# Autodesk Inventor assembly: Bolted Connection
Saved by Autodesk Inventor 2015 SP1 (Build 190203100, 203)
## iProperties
Created: 2014-12
Part Number: Bolted Connection
Document SubType Name: Assembly
Designer: rsheridan
ClientObjectVersion: 1
Author: rsheridan
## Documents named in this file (4)
- \\psf\Home\Documents\Inventor\Sau Paulo Chimnea\Base Assembly\Design Accelerator\Bolted Connection1.iam
- \\psf\Home\Documents\Inventor\Sau Paulo Chimnea\DIN EN ISO 7046-2 H - M5x35 - 8.8 - H1.ipt
- \\psf\Home\Documents\Inventor\Sau Paulo Chimnea\ISO 7089 - 5 - 140 HV(1).ipt
- \\psf\Home\Documents\Inventor\Sau Paulo Chimnea\ISO 4032 - M5ISO.ipt
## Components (9 placed, 3 different names)
1. DIN EN ISO 7046-2 H - M5x35 - 8.8 - H1:1
2. ISO 7089 - 5 - 140 HV(1):1
3. ISO 4032 - M5ISO:1
4. DIN EN ISO 7046-2 H - M5x35 - 8.8 - H1:2
5. DIN EN ISO 7046-2 H - M5x35 - 8.8 - H1:3
6. ISO 7089 - 5 - 140 HV(1):2
7. ISO 7089 - 5 - 140 HV(1):3
8. ISO 4032 - M5ISO:2
9. ISO 4032 - M5ISO:3
